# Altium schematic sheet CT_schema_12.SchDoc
size 147 x 119 mm
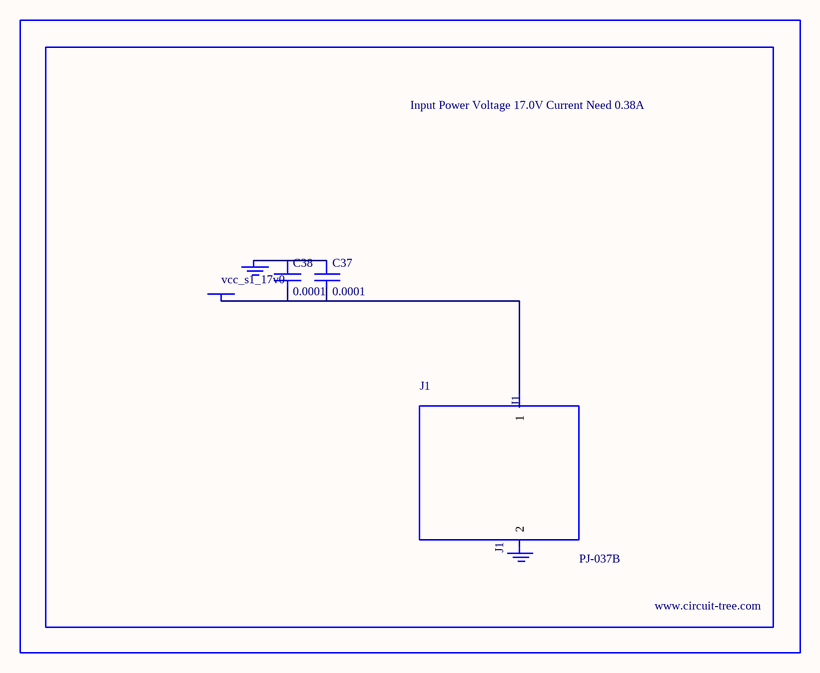
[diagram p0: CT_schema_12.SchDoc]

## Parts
BORDER11  (no value)
C37  0.0001  [EXV-9H]
C38  0.0001  [EXV-9H]
GND_INSTANCE_11_0  (no value)
GND_INSTANCE_11_1  (no value)
J1  PJ-037B  [PJ-037B_PACKAGE]
POWER_INSTANCE_11_0  vcc_s1_17v0

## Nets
NetC37_1: C37.1 C38.1 GND_INSTANCE_11_0.0(GND)
NetC37_2: C37.2 C38.2 J1.1 POWER_INSTANCE_11_0.0(PWR)

Not connected (* = marked no-connect by the designer): GND_INSTANCE_11_1 0(GND); J1 2

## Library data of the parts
BORDER11 = BORDER_PAGE11
C37 C38 = EDK107M035A9HAA
GND_INSTANCE_11_0 GND_INSTANCE_11_1 = GND
POWER_INSTANCE_11_0 = PWR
